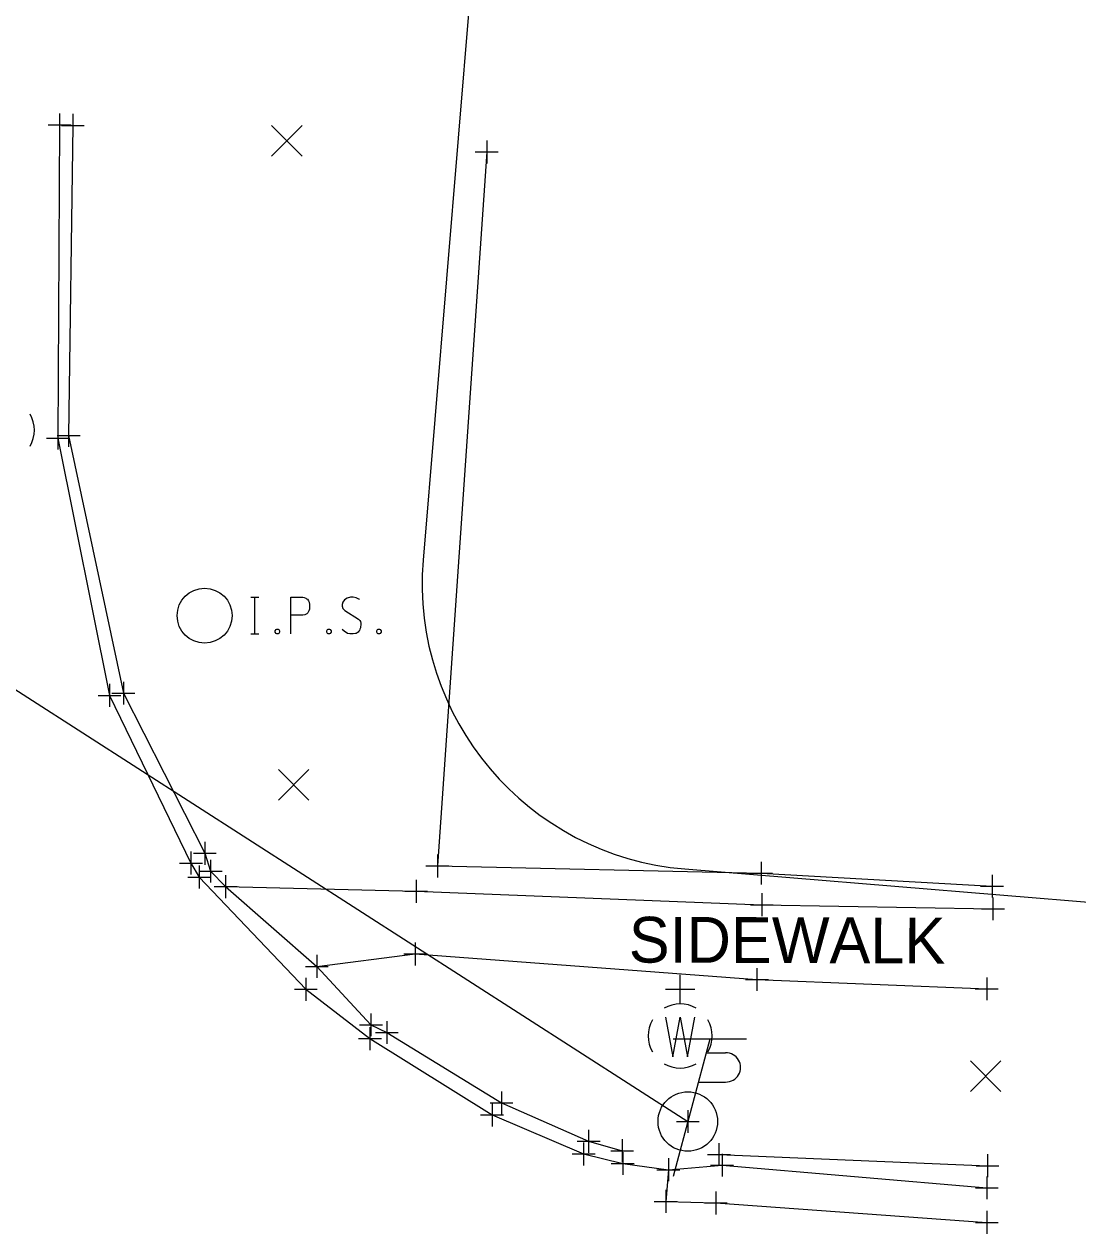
# Model space of a CAD drawing. Extents: x 1380550 to 1381945, y 468927 to 470496.
# Drawn here: x 1381546.4 to 1381592.4, y 469159.6 to 469212.5 of the extents above; entities that cross this region are included whole.
import ezdxf

# ---------------------------------------------------------------- set-up
doc = ezdxf.new("R2010")
doc.units = 0
for name, color, linetype in [('PV_X_Curb', 7, 'Continuous'), ('PV_X_EOP', 7, 'Continuous'), ('PV_X_Walk', 7, 'Continuous'), ('RD_X_Fence', 7, 'Continuous'), ('RD_X_Text', 7, 'Continuous'), ('RW_X_Esmt_General', 7, 'Continuous'), ('SV_P_Mon_Cells_Set', 7, 'Continuous'), ('SV_X_Random_Point', 7, 'Continuous'), ('SV_X_Shot_Marker', 7, 'Continuous'), ('UT_X_Electric', 7, 'Continuous'), ('UT_X_Misc_Cells', 7, 'Continuous'), ('UT_X_Telecom', 7, 'Continuous'), ('UT_X_Water_Cells', 7, 'Continuous')]:
    doc.layers.add(name, color=color, linetype=linetype)

msp = doc.modelspace()

# ---------------------------------------------------------------- linework, layer by layer
at = {"layer": 'PV_X_Curb'}
for points in [[(1381548.49, 469208.03), (1381548.306, 469194.482), (1381550.699, 469183.223), (1381554.254, 469176.228), (1381554.509, 469175.447), (1381555.163, 469174.772), (1381559.145, 469171.286), (1381561.509, 469168.737), (1381562.206, 469168.402), (1381567.213, 469165.329), (1381571.015, 469163.646), (1381572.481, 469163.233)], [(1381576.709, 469163.068), (1381588.441, 469162.58)], [(1381574.504, 469162.404), (1381576.844, 469162.602), (1381588.409, 469161.614)]]:
    msp.add_lwpolyline(points, dxfattribs=at)
at = {"layer": 'PV_X_EOP'}
msp.add_lwpolyline([(1381547.909, 469208.051), (1381547.84, 469194.367), (1381550.09, 469183.128), (1381553.65, 469175.8), (1381554.007, 469175.192), (1381558.668, 469170.29), (1381561.464, 469168.133), (1381566.798, 469164.8), (1381570.8, 469163.096), (1381572.509, 469162.677), (1381574.504, 469162.404), (1381574.384, 469161.02), (1381576.576, 469160.953), (1381588.411, 469160.105)], dxfattribs=at)
at = {"layer": 'PV_X_Walk'}
for points in [[(1381555.163, 469174.772), (1381563.486, 469174.57), (1381578.581, 469173.981), (1381588.68, 469173.803)], [(1381559.145, 469171.286), (1381563.442, 469171.834), (1381578.369, 469170.714), (1381588.407, 469170.306)]]:
    msp.add_lwpolyline(points, dxfattribs=at)
at = {"layer": 'RD_X_Fence'}
msp.add_lwpolyline([(1381566.566, 469206.867), (1381564.411, 469175.674), (1381578.548, 469175.359), (1381588.639, 469174.792)], dxfattribs=at)
at = {"layer": 'RW_X_Esmt_General'}
msp.add_line((1381575.218, 469175.545), (1381603.006, 469173.26), dxfattribs=at)
msp.add_lwpolyline([(1381783.194, 470213.888), (1381648.776, 470217.487), (1381563.79, 469189.032)], dxfattribs=at)
msp.add_arc((1381576.248, 469188.003), 12.5, 175.2761, 265.2761, dxfattribs=at)
at = {"layer": 'SV_P_Mon_Cells_Set'}
for points in [[(1381556.263, 469187.412), (1381556.616, 469187.412)], [(1381556.439, 469185.812), (1381556.439, 469187.412)], [(1381558.005, 469185.812), (1381558.005, 469187.412), (1381558.534, 469187.412), (1381558.589, 469187.4), (1381558.666, 469187.374), (1381558.699, 469187.349), (1381558.732, 469187.324), (1381558.776, 469187.261), (1381558.809, 469187.198), (1381558.831, 469187.097), (1381558.831, 469186.946), (1381558.82, 469186.896), (1381558.798, 469186.82), (1381558.754, 469186.732), (1381558.71, 469186.694), (1381558.677, 469186.669), (1381558.622, 469186.644), (1381558.534, 469186.631), (1381558.005, 469186.631)], [(1381561.014, 469187.299), (1381560.992, 469187.324), (1381560.959, 469187.349), (1381560.86, 469187.387), (1381560.738, 469187.412), (1381560.65, 469187.412), (1381560.617, 469187.412), (1381560.474, 469187.374), (1381560.353, 469187.299), (1381560.275, 469187.198), (1381560.253, 469187.097), (1381560.253, 469187.022), (1381560.275, 469186.921), (1381560.364, 469186.833), (1381560.97, 469186.455), (1381561.025, 469186.405), (1381561.047, 469186.354), (1381561.069, 469186.279), (1381561.069, 469186.203), (1381561.058, 469186.127), (1381561.047, 469186.077), (1381561.025, 469186.014), (1381561.003, 469185.964), (1381560.981, 469185.926), (1381560.948, 469185.888), (1381560.915, 469185.863), (1381560.871, 469185.838), (1381560.838, 469185.825), (1381560.738, 469185.812), (1381560.584, 469185.812), (1381560.485, 469185.838), (1381560.341, 469185.926), (1381560.253, 469186.001)], [(1381557.398, 469186.027), (1381557.453, 469186.027), (1381557.487, 469186.001), (1381557.52, 469185.951), (1381557.52, 469185.888), (1381557.487, 469185.838), (1381557.453, 469185.812), (1381557.398, 469185.812), (1381557.365, 469185.838), (1381557.332, 469185.888), (1381557.332, 469185.951), (1381557.365, 469186.001), (1381557.398, 469186.027)], [(1381559.647, 469186.027), (1381559.702, 469186.027), (1381559.735, 469186.001), (1381559.768, 469185.951), (1381559.768, 469185.888), (1381559.735, 469185.838), (1381559.702, 469185.812), (1381559.647, 469185.812), (1381559.614, 469185.838), (1381559.581, 469185.888), (1381559.581, 469185.951), (1381559.614, 469186.001), (1381559.647, 469186.027)], [(1381561.83, 469186.027), (1381561.885, 469186.027), (1381561.918, 469186.001), (1381561.951, 469185.951), (1381561.951, 469185.888), (1381561.918, 469185.838), (1381561.885, 469185.812), (1381561.83, 469185.812), (1381561.796, 469185.838), (1381561.764, 469185.888), (1381561.764, 469185.951), (1381561.796, 469186.001), (1381561.83, 469186.027)], [(1381556.263, 469185.812), (1381556.616, 469185.812)]]:
    msp.add_lwpolyline(points, dxfattribs=at)
msp.add_circle((1381554.244, 469186.611), 1.2, dxfattribs=at)
at = {"layer": 'SV_X_Random_Point'}
for p, q in [((1381557.169, 469206.688), (1381558.503, 469208.023)), ((1381557.169, 469208.023), (1381558.503, 469206.688)), ((1381557.47, 469178.556), (1381558.804, 469179.891)), ((1381557.47, 469179.891), (1381558.804, 469178.556)), ((1381587.693, 469165.821), (1381589.027, 469167.156)), ((1381587.693, 469167.156), (1381589.027, 469165.821))]:
    msp.add_line(p, q, dxfattribs=at)
at = {"layer": 'SV_X_Shot_Marker'}
for p, q in [((1381547.909, 469208.551), (1381547.909, 469207.551)), ((1381548.49, 469208.53), (1381548.49, 469207.53)), ((1381547.409, 469208.051), (1381548.409, 469208.051)), ((1381547.909, 469208.051), (1381547.909, 469208.051)), ((1381547.99, 469208.03), (1381548.99, 469208.03)), ((1381548.49, 469208.03), (1381548.49, 469208.03)), ((1381566.566, 469207.367), (1381566.566, 469206.367)), ((1381566.066, 469206.867), (1381567.066, 469206.867)), ((1381566.566, 469206.867), (1381566.566, 469206.867)), ((1381547.84, 469194.867), (1381547.84, 469193.867)), ((1381547.84, 469194.867), (1381547.84, 469193.867)), ((1381548.306, 469194.982), (1381548.306, 469193.982)), ((1381548.306, 469194.982), (1381548.306, 469193.982)), ((1381547.34, 469194.367), (1381548.34, 469194.367)), ((1381547.34, 469194.367), (1381548.34, 469194.367)), ((1381547.806, 469194.482), (1381548.806, 469194.482)), ((1381547.806, 469194.482), (1381548.806, 469194.482)), ((1381547.84, 469194.367), (1381547.84, 469194.367)), ((1381547.84, 469194.367), (1381547.84, 469194.367)), ((1381548.306, 469194.482), (1381548.306, 469194.482)), ((1381548.306, 469194.482), (1381548.306, 469194.482)), ((1381550.09, 469183.628), (1381550.09, 469182.628)), ((1381550.199, 469183.223), (1381551.199, 469183.223)), ((1381550.699, 469183.723), (1381550.699, 469182.723)), ((1381550.699, 469183.223), (1381550.699, 469183.223)), ((1381549.59, 469183.128), (1381550.59, 469183.128)), ((1381550.09, 469183.128), (1381550.09, 469183.128)), ((1381554.254, 469176.728), (1381554.254, 469175.728)), ((1381554.254, 469176.728), (1381554.254, 469175.728)), ((1381553.65, 469176.3), (1381553.65, 469175.3)), ((1381553.65, 469176.3), (1381553.65, 469175.3)), ((1381553.754, 469176.228), (1381554.754, 469176.228)), ((1381553.754, 469176.228), (1381554.754, 469176.228)), ((1381554.254, 469176.228), (1381554.254, 469176.228)), ((1381554.254, 469176.228), (1381554.254, 469176.228)), ((1381554.509, 469175.947), (1381554.509, 469174.947)), ((1381564.411, 469176.174), (1381564.411, 469175.174)), ((1381578.548, 469175.859), (1381578.548, 469174.859)), ((1381553.15, 469175.8), (1381554.15, 469175.8)), ((1381553.15, 469175.8), (1381554.15, 469175.8)), ((1381553.65, 469175.8), (1381553.65, 469175.8)), ((1381553.65, 469175.8), (1381553.65, 469175.8)), ((1381554.007, 469175.692), (1381554.007, 469174.692)), ((1381554.009, 469175.447), (1381555.009, 469175.447)), ((1381554.509, 469175.447), (1381554.509, 469175.447)), ((1381563.911, 469175.674), (1381564.911, 469175.674)), ((1381564.411, 469175.674), (1381564.411, 469175.674)), ((1381578.048, 469175.359), (1381579.048, 469175.359)), ((1381578.548, 469175.359), (1381578.548, 469175.359)), ((1381588.639, 469175.292), (1381588.639, 469174.292)), ((1381553.507, 469175.192), (1381554.507, 469175.192)), ((1381554.007, 469175.192), (1381554.007, 469175.192)), ((1381554.663, 469174.772), (1381555.663, 469174.772)), ((1381554.663, 469174.772), (1381555.663, 469174.772)), ((1381555.163, 469175.272), (1381555.163, 469174.272)), ((1381555.163, 469175.272), (1381555.163, 469174.272)), ((1381555.163, 469174.772), (1381555.163, 469174.772)), ((1381555.163, 469174.772), (1381555.163, 469174.772)), ((1381563.486, 469175.07), (1381563.486, 469174.07)), ((1381588.139, 469174.792), (1381589.139, 469174.792)), ((1381588.639, 469174.792), (1381588.639, 469174.792)), ((1381562.986, 469174.57), (1381563.986, 469174.57)), ((1381563.486, 469174.57), (1381563.486, 469174.57)), ((1381578.581, 469174.481), (1381578.581, 469173.481)), ((1381588.68, 469174.303), (1381588.68, 469173.303)), ((1381578.081, 469173.981), (1381579.081, 469173.981)), ((1381578.581, 469173.981), (1381578.581, 469173.981)), ((1381588.18, 469173.803), (1381589.18, 469173.803)), ((1381588.68, 469173.803), (1381588.68, 469173.803)), ((1381563.442, 469172.334), (1381563.442, 469171.334)), ((1381559.145, 469171.786), (1381559.145, 469170.786)), ((1381559.145, 469171.786), (1381559.145, 469170.786)), ((1381562.942, 469171.834), (1381563.942, 469171.834)), ((1381563.442, 469171.834), (1381563.442, 469171.834)), ((1381558.645, 469171.286), (1381559.645, 469171.286)), ((1381558.645, 469171.286), (1381559.645, 469171.286)), ((1381559.145, 469171.286), (1381559.145, 469171.286)), ((1381559.145, 469171.286), (1381559.145, 469171.286)), ((1381578.369, 469171.214), (1381578.369, 469170.214)), ((1381558.668, 469170.79), (1381558.668, 469169.79)), ((1381577.869, 469170.714), (1381578.869, 469170.714)), ((1381578.369, 469170.714), (1381578.369, 469170.714)), ((1381588.407, 469170.806), (1381588.407, 469169.806)), ((1381558.168, 469170.29), (1381559.168, 469170.29)), ((1381558.668, 469170.29), (1381558.668, 469170.29)), ((1381587.907, 469170.306), (1381588.907, 469170.306)), ((1381588.407, 469170.306), (1381588.407, 469170.306)), ((1381561.509, 469169.237), (1381561.509, 469168.237)), ((1381561.009, 469168.737), (1381562.009, 469168.737)), ((1381561.464, 469168.633), (1381561.464, 469167.633)), ((1381561.509, 469168.737), (1381561.509, 469168.737)), ((1381562.206, 469168.902), (1381562.206, 469167.902)), ((1381560.964, 469168.133), (1381561.964, 469168.133)), ((1381561.464, 469168.133), (1381561.464, 469168.133)), ((1381561.706, 469168.402), (1381562.706, 469168.402)), ((1381562.206, 469168.402), (1381562.206, 469168.402)), ((1381567.213, 469165.829), (1381567.213, 469164.829)), ((1381566.713, 469165.329), (1381567.713, 469165.329)), ((1381566.798, 469165.3), (1381566.798, 469164.3)), ((1381567.213, 469165.329), (1381567.213, 469165.329)), ((1381566.298, 469164.8), (1381567.298, 469164.8)), ((1381566.798, 469164.8), (1381566.798, 469164.8)), ((1381575.349, 469165.011), (1381575.349, 469164.011)), ((1381575.349, 469165.011), (1381575.349, 469164.011)), ((1381574.849, 469164.511), (1381575.849, 469164.511)), ((1381574.849, 469164.511), (1381575.849, 469164.511)), ((1381575.349, 469164.511), (1381575.349, 469164.511)), ((1381575.349, 469164.511), (1381575.349, 469164.511)), ((1381571.015, 469164.146), (1381571.015, 469163.146)), ((1381572.481, 469163.733), (1381572.481, 469162.733)), ((1381570.515, 469163.646), (1381571.515, 469163.646)), ((1381570.8, 469163.596), (1381570.8, 469162.596)), ((1381571.015, 469163.646), (1381571.015, 469163.646)), ((1381571.981, 469163.233), (1381572.981, 469163.233)), ((1381572.481, 469163.233), (1381572.481, 469163.233)), ((1381572.509, 469163.177), (1381572.509, 469162.177)), ((1381576.709, 469163.568), (1381576.709, 469162.568)), ((1381570.3, 469163.096), (1381571.3, 469163.096)), ((1381570.8, 469163.096), (1381570.8, 469163.096)), ((1381572.009, 469162.677), (1381573.009, 469162.677)), ((1381572.509, 469162.677), (1381572.509, 469162.677)), ((1381574.504, 469162.904), (1381574.504, 469161.904)), ((1381574.504, 469162.904), (1381574.504, 469161.904)), ((1381576.209, 469163.068), (1381577.209, 469163.068)), ((1381576.709, 469163.068), (1381576.709, 469163.068)), ((1381576.844, 469163.102), (1381576.844, 469162.102)), ((1381588.441, 469163.08), (1381588.441, 469162.08)), ((1381574.004, 469162.404), (1381575.004, 469162.404)), ((1381574.004, 469162.404), (1381575.004, 469162.404)), ((1381574.504, 469162.404), (1381574.504, 469162.404)), ((1381574.504, 469162.404), (1381574.504, 469162.404)), ((1381576.344, 469162.602), (1381577.344, 469162.602)), ((1381576.844, 469162.602), (1381576.844, 469162.602)), ((1381587.941, 469162.58), (1381588.941, 469162.58)), ((1381588.409, 469162.114), (1381588.409, 469161.114)), ((1381588.441, 469162.58), (1381588.441, 469162.58)), ((1381587.909, 469161.614), (1381588.909, 469161.614)), ((1381588.409, 469161.614), (1381588.409, 469161.614)), ((1381574.384, 469161.52), (1381574.384, 469160.52)), ((1381576.576, 469161.453), (1381576.576, 469160.453)), ((1381573.884, 469161.02), (1381574.884, 469161.02)), ((1381574.384, 469161.02), (1381574.384, 469161.02)), ((1381576.076, 469160.953), (1381577.076, 469160.953)), ((1381576.576, 469160.953), (1381576.576, 469160.953)), ((1381588.411, 469160.605), (1381588.411, 469159.605)), ((1381587.911, 469160.105), (1381588.911, 469160.105)), ((1381588.411, 469160.105), (1381588.411, 469160.105))]:
    msp.add_line(p, q, dxfattribs=at)
at = {"layer": 'UT_X_Electric'}
msp.add_lwpolyline([(1381515.279, 469203.101), (1381575.349, 469164.511)], dxfattribs=at)
at = {"layer": 'UT_X_Misc_Cells'}
for p, q in [((1381576.312, 469168.111), (1381574.706, 469162.111)), ((1381577.912, 469168.111), (1381574.712, 469168.111)), ((1381576.152, 469167.511), (1381577.002, 469167.511)), ((1381575.811, 469166.236), (1381577.002, 469166.236))]:
    msp.add_line(p, q, dxfattribs=at)
msp.add_circle((1381575.349, 469164.511), 1.3, dxfattribs=at)
msp.add_arc((1381577.015, 469166.874), 0.638, 268.8767, 91.1233, dxfattribs=at)
at = {"layer": 'UT_X_Telecom'}
msp.add_lwpolyline([(1381515.279, 469203.101), (1381575.349, 469164.511)], dxfattribs=at)
at = {"layer": 'UT_X_Water_Cells'}
for p, q in [((1381575.017, 469169.646), (1381575.017, 469170.918)), ((1381575.652, 469170.283), (1381574.38, 469170.283)), ((1381575.017, 469168.246), (1381575.017, 469168.246))]:
    msp.add_line(p, q, dxfattribs=at)
msp.add_lwpolyline([(1381574.38, 469169.066), (1381574.699, 469167.343), (1381575.017, 469169.066), (1381575.337, 469167.343), (1381575.654, 469169.066)], dxfattribs=at)
for centre, start, end in [((1381545.409, 469194.715), 330.0184, 29.9816), ((1381575.017, 469168.248), 60.0184, 120.0157), ((1381575.017, 469168.248), 150.0184, 209.9816), ((1381575.017, 469168.248), 330.0184, 29.9816), ((1381575.017, 469168.248), 239.9843, 299.9816)]:
    msp.add_arc(centre, 1.4, start, end, dxfattribs=at)

# ---------------------------------------------------------------- texts
at = {"layer": 'RD_X_Text'}
msp.add_text('SIDEWALK', height=2, rotation=359.8186, dxfattribs=at).set_placement((1381572.771, 469171.456))

doc.saveas('drawing.dxf')
